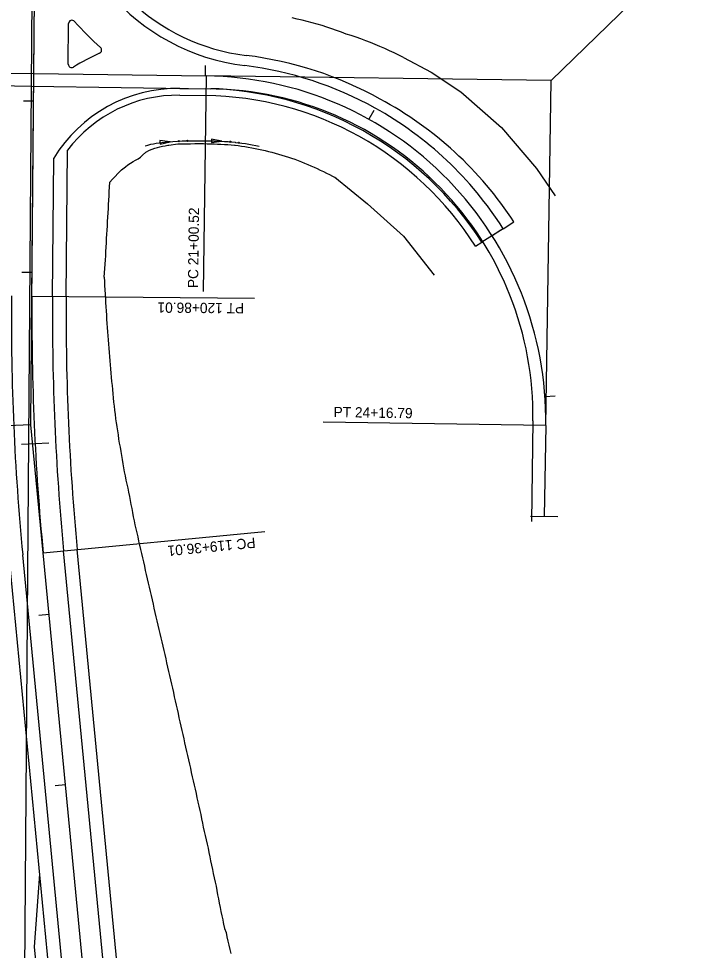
# Model space of a CAD drawing. Extents: x 1311167 to 1314552, y 2087587 to 2090602.
# Drawn here: x 1313998 to 1314395, y 2089699 to 2090242 of the extents above; entities that cross this region are included whole.
import ezdxf

# ---------------------------------------------------------------- set-up
doc = ezdxf.new("R2010")
doc.units = 0
for name, color, linetype in [('R_Bridge', 7, 'Continuous'), ('R_Guardrail', 7, 'Continuous'), ('R_Horz Alg Annot_Side Road', 7, 'Continuous'), ('R_Horz Alg Stationing', 7, 'Continuous'), ('R_Proposed Road', 7, 'Continuous'), ('R_Shld_GR', 7, 'Continuous'), ('R_Shoulder', 7, 'Continuous'), ('S_DITCHLINE', 7, 'Continuous'), ('S_EDGE_CONCRETE', 7, 'Continuous'), ('S_EDGE_PAVEMENT', 7, 'Continuous'), ('S_PAVEMENT_CROWN', 7, 'Continuous')]:
    doc.layers.add(name, color=color, linetype=linetype)

msp = doc.modelspace()

# ---------------------------------------------------------------- linework, layer by layer
at = {"layer": 'R_Bridge'}
for points in [[(1314000.32, 2090194.52), (1314006.32, 2090194.46)], [(1313999.45, 2090094.52), (1314005.45, 2090094.47)], [(1313999.17, 2089994.09), (1314015.15, 2089994.91)], [(1314009.35, 2089894.27), (1314015.32, 2089894.85)], [(1314018.93, 2089794.73), (1314024.9, 2089795.31)]]:
    msp.add_lwpolyline(points, dxfattribs=at)
at = {"layer": 'R_Guardrail'}
for points in [[(1314011.87, 2089930.69), (1314004.67, 2090005.41), (1314005.33, 2090080.47)], [(1314005.33, 2090080.47), (1314135.32, 2090079.34)], [(1314004.67, 2090005.41), (1313884.79, 2090000.17)], [(1314011.87, 2089930.69), (1314141.27, 2089943.15)]]:
    msp.add_lwpolyline(points, dxfattribs=at)
at = {"layer": 'R_Horz Alg Annot_Side Road'}
msp.add_line((1314007.85, 2089690.6), (1314006.9, 2089700.55), dxfattribs=at)
msp.add_lwpolyline([(1314006.9, 2089700.55), (1314009.84, 2089743.07)], dxfattribs=at)
at = {"layer": 'R_Horz Alg Stationing'}
for p, q in [((1313999.49, 2089462.84), (1314005.79, 2090288.55)), ((1313906.36, 2090204.65), (1314005.14, 2090203.15)), ((1314005.14, 2090203.15), (1314109.86, 2090201.56)), ((1314297.9, 2090007.65), (1314296.99, 2089948.94))]:
    msp.add_line(p, q, dxfattribs=at)
msp.add_arc((1314106.95, 2090010.61), 190.97, 359.1125, 89.1292, dxfattribs=at)
at = {"layer": 'R_Proposed Road'}
for p, q in [((1314005.29, 2090076.56), (1314006.99, 2090271.25)), ((1314005.33, 2090080.47), (1314006.99, 2090271.25)), ((1314005.33, 2090080.47), (1314006.99, 2090271.25)), ((1313908.73, 2090211.67), (1314006.46, 2090210.39)), ((1313908.73, 2090211.67), (1314006.46, 2090210.39)), ((1314006.46, 2090210.39), (1314106.97, 2090209.08)), ((1314006.46, 2090210.39), (1314106.97, 2090209.08)), ((1314305.36, 2090004.94), (1314304.53, 2089951.74)), ((1314305.36, 2090004.94), (1314304.53, 2089951.74)), ((1314055.57, 2089476.83), (1314011.87, 2089930.69)), ((1314055.57, 2089476.83), (1314011.87, 2089930.69))]:
    msp.add_line(p, q, dxfattribs=at)
for centre, radius, start, end in [((1314104.34, 2090008.05), 201.04, 359.1125, 89.25), ((1314104.34, 2090008.05), 201.04, 359.1125, 89.25), ((1315437.67, 2090067.97), 1432.39, 179.5, 185.5), ((1315437.67, 2090067.97), 1432.39, 179.5, 185.5)]:
    msp.add_arc(centre, radius, start, end, dxfattribs=at)
at = {"layer": 'R_Shld_GR'}
for points in [[(1314308.48, 2090206.44), (1314394.53, 2090290.07)], [(1314106.97, 2090209.08), (1314105.32, 2090083.14)], [(1314305.36, 2090004.94), (1314308.48, 2090206.44), (1314106.97, 2090209.08)], [(1314305.36, 2090004.94), (1314175.37, 2090006.95)]]:
    msp.add_lwpolyline(points, dxfattribs=at)
at = {"layer": 'R_Shoulder'}
for points in [[(1314106.53, 2090215.08), (1314106.45, 2090209.08)], [(1314205.04, 2090188.96), (1314202.12, 2090183.71)], [(1314279.15, 2090118.99), (1314274.09, 2090115.77)], [(1314310.9, 2090022.13), (1314304.91, 2090021.72)], [(1314312.53, 2089951.62), (1314296.53, 2089951.86)], [(1314312.53, 2089951.62), (1314296.53, 2089951.86)]]:
    msp.add_lwpolyline(points, dxfattribs=at)
at = {"layer": 'S_DITCHLINE'}
for p, q in [((1314086.13, 2090170.61), (1314080.08, 2090171.29)), ((1314080.08, 2090171.29), (1314080.21, 2090169.18)), ((1314080.21, 2090169.18), (1314086.13, 2090170.61)), ((1314110.19, 2090172.22), (1314110.12, 2090170.11)), ((1314110.12, 2090170.11), (1314116.15, 2090170.96)), ((1314116.15, 2090170.96), (1314110.19, 2090172.22))]:
    msp.add_line(p, q, dxfattribs=at)
for points in [[(1314071.37, 2090168.22), (1314073.02, 2090168.7), (1314074.67, 2090169.13), (1314076.32, 2090169.49), (1314077.95, 2090169.8), (1314079.58, 2090170.05), (1314081.21, 2090170.25), (1314082.82, 2090170.4), (1314084.43, 2090170.5), (1314084.96, 2090170.52), (1314092.99, 2090171.07), (1314095.49, 2090171.09), (1314097.99, 2090171.11), (1314100.49, 2090171.13), (1314102.99, 2090171.14), (1314105.49, 2090171.15), (1314107.7, 2090171.16), (1314109.73, 2090171.15), (1314111.76, 2090171.11), (1314113.79, 2090171.04), (1314115.82, 2090170.95), (1314117.85, 2090170.82), (1314119.87, 2090170.67), (1314121.9, 2090170.5), (1314123.92, 2090170.29), (1314124.22, 2090170.26), (1314125.94, 2090170.06), (1314127.95, 2090169.8), (1314129.97, 2090169.51), (1314131.98, 2090169.2), (1314133.98, 2090168.86), (1314135.98, 2090168.49), (1314137.98, 2090168.09)], [(1314071.37, 2090168.22), (1314073.02, 2090168.7), (1314074.67, 2090169.13), (1314076.32, 2090169.49), (1314077.95, 2090169.8), (1314079.58, 2090170.05), (1314081.21, 2090170.25), (1314082.82, 2090170.4), (1314084.43, 2090170.5), (1314084.96, 2090170.52), (1314086.13, 2090170.6)], [(1314101.12, 2090171.13), (1314101.15, 2090171.13)], [(1314101.15, 2090171.13), (1314102.99, 2090171.14), (1314105.49, 2090171.15), (1314107.7, 2090171.16), (1314109.73, 2090171.15), (1314111.76, 2090171.11), (1314113.79, 2090171.04), (1314115.82, 2090170.95), (1314116.15, 2090170.93)], [(1314131.06, 2090169.34), (1314131.1, 2090169.34)], [(1314131.1, 2090169.34), (1314131.98, 2090169.2), (1314133.98, 2090168.86), (1314135.98, 2090168.49), (1314137.98, 2090168.09)]]:
    msp.add_lwpolyline(points, dxfattribs=at)
for centre in [(1314091.12, 2090170.98), (1314096.13, 2090171.13), (1314121.14, 2090170.6), (1314126.13, 2090170.07)]:
    msp.add_circle(centre, 0.375, dxfattribs=at)
at = {"layer": 'S_EDGE_CONCRETE'}
for points in [[(1314222.24, 2090219.87), (1314219.53, 2090221.2), (1314216.81, 2090222.5), (1314214.08, 2090223.76), (1314211.33, 2090224.99), (1314208.57, 2090226.19), (1314205.8, 2090227.36), (1314203.01, 2090228.49), (1314200.22, 2090229.61), (1314197.41, 2090230.67), (1314194.59, 2090231.69), (1314191.71, 2090232.57), (1314188.84, 2090233.45), (1314186.1, 2090234.65), (1314183.27, 2090235.64), (1314180.43, 2090236.58), (1314177.57, 2090237.49), (1314174.72, 2090238.4), (1314171.84, 2090239.24), (1314168.95, 2090240.03), (1314166.06, 2090240.79), (1314163.16, 2090241.54), (1314160.25, 2090242.26), (1314157.33, 2090242.9)], [(1314222.24, 2090219.87), (1314238.55, 2090211.26), (1314255.87, 2090199.73), (1314279.52, 2090178.98), (1314299.98, 2090154.96), (1314310.86, 2090139.11)], [(1314071.74, 2090164.5), (1314074.06, 2090165.64), (1314075.54, 2090166.29), (1314077.03, 2090166.86), (1314078.55, 2090167.31), (1314080.07, 2090167.7), (1314081.6, 2090168.04), (1314083.13, 2090168.31), (1314084.66, 2090168.53), (1314085.17, 2090168.59), (1314090.46, 2090169.39), (1314092.96, 2090169.42), (1314095.47, 2090169.45), (1314097.97, 2090169.47), (1314100.47, 2090169.5), (1314102.97, 2090169.52), (1314105.47, 2090169.5), (1314107.67, 2090169.48), (1314109.68, 2090169.43), (1314111.68, 2090169.36), (1314113.69, 2090169.28), (1314115.7, 2090169.18), (1314117.7, 2090169.07), (1314119.71, 2090168.92), (1314121.71, 2090168.76), (1314123.71, 2090168.57), (1314124.01, 2090168.54), (1314125.71, 2090168.35), (1314127.71, 2090168.11), (1314129.7, 2090167.81), (1314131.68, 2090167.48), (1314133.66, 2090167.12), (1314135.64, 2090166.74), (1314137.61, 2090166.34)], [(1314050.75, 2090147.05), (1314052.35, 2090148.85), (1314054.01, 2090150.4), (1314055.43, 2090152.02), (1314056.85, 2090153.5), (1314057.55, 2090154.19), (1314058.34, 2090154.81), (1314059.87, 2090155.97), (1314061.38, 2090157.05), (1314062.87, 2090158.06), (1314064.36, 2090159), (1314065.83, 2090159.88), (1314067.3, 2090160.71), (1314068.71, 2090161.59), (1314069.94, 2090162.82), (1314071.74, 2090164.5)], [(1314137.61, 2090166.34), (1314139.57, 2090165.91), (1314141.53, 2090165.45), (1314143.48, 2090164.97), (1314145.43, 2090164.47), (1314147.37, 2090163.95), (1314149.31, 2090163.41), (1314151.24, 2090162.85), (1314153.17, 2090162.26), (1314155.08, 2090161.66), (1314156.99, 2090161.03), (1314158.9, 2090160.38), (1314160.8, 2090159.7), (1314162.67, 2090158.98), (1314164.53, 2090158.21), (1314166.38, 2090157.42), (1314168.22, 2090156.6), (1314170.06, 2090155.79), (1314171.89, 2090154.97), (1314173.72, 2090154.12), (1314175.53, 2090153.26), (1314177.34, 2090152.37), (1314179.14, 2090151.47), (1314180.92, 2090150.54), (1314182.7, 2090149.6), (1314183.03, 2090149.42)], [(1314047.49, 2090091.6), (1314047.64, 2090094.1), (1314047.97, 2090096.6), (1314048.11, 2090099.1), (1314048.25, 2090101.6), (1314048.38, 2090104.09), (1314048.52, 2090106.59), (1314048.66, 2090109.09), (1314048.8, 2090111.59), (1314048.94, 2090114.09), (1314049.08, 2090116.59), (1314049.23, 2090119.09), (1314049.38, 2090121.59), (1314049.53, 2090124.09), (1314049.67, 2090126.58), (1314049.81, 2090129.08), (1314049.94, 2090131.58), (1314050.06, 2090134.08), (1314050.19, 2090136.58), (1314050.33, 2090139.08), (1314050.46, 2090141.58), (1314050.6, 2090144.08), (1314050.75, 2090147.05)], [(1314182.14, 2090149.89), (1314201.36, 2090134.34), (1314222.29, 2090115.49), (1314240.23, 2090092.69)], [(1314047.49, 2090091.6), (1314047.62, 2090089.1), (1314047.75, 2090086.6), (1314047.89, 2090084.1), (1314048.04, 2090081.6), (1314048.19, 2090079.13), (1314048.33, 2090076.7), (1314048.48, 2090074.27), (1314048.62, 2090071.85), (1314048.78, 2090069.42), (1314048.94, 2090067), (1314049.11, 2090064.58), (1314049.29, 2090062.15), (1314049.48, 2090059.73), (1314049.66, 2090057.31), (1314049.84, 2090054.89), (1314050.02, 2090052.47), (1314050.21, 2090050.05), (1314050.4, 2090047.63), (1314050.59, 2090045.21), (1314050.79, 2090042.79), (1314050.99, 2090040.38), (1314051.19, 2090037.96), (1314051.41, 2090035.54), (1314051.63, 2090033.13), (1314051.84, 2090030.71), (1314052.07, 2090028.3), (1314052.29, 2090025.88), (1314052.52, 2090023.47), (1314052.76, 2090021.06), (1314053, 2090018.65), (1314053.28, 2090016.24), (1314053.58, 2090013.83), (1314053.89, 2090011.42), (1314054.2, 2090009.02), (1314054.38, 2090007.58), (1314054.52, 2090006.61), (1314054.87, 2090004.21), (1314055.22, 2090001.81), (1314055.58, 2089999.41), (1314055.94, 2089997.01), (1314056.33, 2089994.61), (1314056.78, 2089992.22), (1314057.22, 2089989.82), (1314057.61, 2089987.43), (1314058.02, 2089985.04), (1314058.43, 2089982.64), (1314058.84, 2089980.25), (1314059.26, 2089977.87), (1314059.73, 2089975.48), (1314060.24, 2089973.1), (1314060.76, 2089970.72), (1314061.28, 2089968.34), (1314061.75, 2089965.96), (1314062.2, 2089963.58), (1314062.65, 2089961.2), (1314063.11, 2089958.82), (1314063.58, 2089956.45), (1314064.05, 2089954.07), (1314064.52, 2089951.7), (1314065, 2089949.33), (1314065.49, 2089946.95), (1314065.99, 2089944.58), (1314066.53, 2089942.22), (1314067.07, 2089939.86), (1314067.61, 2089937.5), (1314068.16, 2089935.1), (1314068.72, 2089932.64), (1314069.28, 2089930.18), (1314069.84, 2089927.72), (1314070.41, 2089925.27), (1314070.97, 2089922.81), (1314071.51, 2089920.35), (1314072.05, 2089917.89), (1314072.61, 2089915.43), (1314073.18, 2089912.98), (1314073.75, 2089910.52), (1314074.32, 2089908.06), (1314074.89, 2089905.61), (1314075.47, 2089903.15), (1314076.03, 2089900.69), (1314076.58, 2089898.23), (1314077.13, 2089895.78), (1314077.7, 2089893.32), (1314078.27, 2089890.86), (1314078.85, 2089888.41), (1314079.43, 2089885.95), (1314080.02, 2089883.49), (1314080.59, 2089881.04), (1314081.16, 2089878.58), (1314081.73, 2089876.12), (1314082.29, 2089873.67), (1314082.86, 2089871.21), (1314083.42, 2089868.75), (1314083.98, 2089866.3), (1314084.54, 2089863.84), (1314085.1, 2089861.38), (1314085.67, 2089858.92), (1314086.24, 2089856.47), (1314086.8, 2089854.01), (1314087.35, 2089851.55), (1314087.9, 2089849.09), (1314088.45, 2089846.63), (1314088.99, 2089844.17), (1314089.53, 2089841.71), (1314090.07, 2089839.26), (1314090.63, 2089836.8), (1314091.19, 2089834.34), (1314091.74, 2089831.88), (1314092.3, 2089829.42), (1314092.85, 2089826.96), (1314093.39, 2089824.5), (1314093.93, 2089822.05), (1314094.47, 2089819.59), (1314095.03, 2089817.13), (1314095.59, 2089814.67), (1314096.15, 2089812.21), (1314096.71, 2089809.76), (1314097.27, 2089807.3), (1314097.83, 2089804.84), (1314098.39, 2089802.38), (1314098.95, 2089799.92), (1314099.5, 2089797.47), (1314100.04, 2089795.01), (1314100.58, 2089792.55), (1314101.13, 2089790.09), (1314101.69, 2089787.63), (1314102.25, 2089785.17), (1314102.26, 2089785.11), (1314102.81, 2089782.72), (1314103.37, 2089780.26), (1314103.89, 2089777.8), (1314104.37, 2089775.33), (1314104.85, 2089772.87), (1314105.38, 2089770.41), (1314105.95, 2089767.95), (1314106.52, 2089765.49), (1314107.08, 2089763.03), (1314107.65, 2089760.58), (1314108.21, 2089758.12), (1314108.7, 2089755.66), (1314109.16, 2089753.19), (1314109.63, 2089750.72), (1314110.13, 2089748.26), (1314110.67, 2089745.8), (1314111.22, 2089743.34), (1314111.77, 2089740.88), (1314112.31, 2089738.42), (1314112.85, 2089735.96), (1314113.3, 2089733.49), (1314113.75, 2089731.03), (1314114.19, 2089728.56), (1314114.67, 2089726.09), (1314115.2, 2089723.63), (1314115.72, 2089721.17), (1314116.25, 2089718.71), (1314116.77, 2089716.25), (1314117.08, 2089714.78), (1314117.27, 2089713.78), (1314117.7, 2089711.31), (1314118.65, 2089708.94), (1314118.66, 2089708.89), (1314119.17, 2089706.43), (1314119.7, 2089703.97), (1314120.29, 2089701.52), (1314120.87, 2089699.06), (1314121.46, 2089696.61)]]:
    msp.add_lwpolyline(points, dxfattribs=at)
at = {"layer": 'S_EDGE_PAVEMENT'}
for p, q in [((1314091.71, 2090197.77), (1314106.82, 2090197.58)), ((1314025.33, 2090080.3), (1314026.07, 2090165.68)), ((1314280.55, 2090119.87), (1314286.77, 2090123.82)), ((1314264.38, 2090109.61), (1314268, 2090111.91)), ((1314075.48, 2089478.75), (1314031.77, 2089932.6)), ((1314035.66, 2089474.91), (1313991.96, 2089928.77))]:
    msp.add_line(p, q, dxfattribs=at)
for centre, radius, start, end in [((1314144.91, 2090339.12), 119, 189.5746, 263.0143), ((1314104.34, 2090008.05), 214.54, 60.8986, 82.9962), ((1314090.65, 2090116.78), 81, 89.25, 142.8665), ((1314104.34, 2090008.05), 189.54, 60.8986, 89.25), ((1314107.14, 2090006.52), 214.54, 33.145, 61.7515), ((1314104.34, 2090008.05), 189.54, 32.3985, 60.8986), ((1315437.67, 2090067.97), 1412.39, 179.5, 185.5)]:
    msp.add_arc(centre, radius, start, end, dxfattribs=at)
at = {"layer": 'S_PAVEMENT_CROWN'}
for p, q in [((1314026.51, 2090215.93), (1314026.72, 2090239.59)), ((1314091.76, 2090201.77), (1314106.88, 2090201.58)), ((1314017.33, 2090080.37), (1314018.03, 2090160.96)), ((1314280.55, 2090119.87), (1314267.99, 2090111.91)), ((1314043.62, 2089475.68), (1313999.92, 2089929.54)), ((1314067.51, 2089477.98), (1314023.81, 2089931.84))]:
    msp.add_line(p, q, dxfattribs=at)
for centre, radius, start, end in [((1314144.91, 2090339.12), 125, 178.9726, 263.0143), ((1314028.72, 2090239.57), 2, 40.5871, 179.5), ((1314144.91, 2090339.12), 151, 220.5871, 228.7474), ((1314044.02, 2090224.09), 2, 293.4847, 48.7474), ((1314090.65, 2090116.78), 115, 113.4847, 122.079), ((1314028.51, 2090215.92), 2, 179.5, 302.079), ((1314104.34, 2090008.05), 208.54, 60.8986, 83.0143), ((1314090.65, 2090116.78), 85, 89.25, 148.6847), ((1314104.34, 2090008.05), 193.54, 60.8986, 89.25), ((1314104.62, 2090007.9), 208.54, 32.4747, 60.9853), ((1314104.86, 2090007.77), 193.54, 32.5535, 61.0751), ((1315437.67, 2090067.97), 1444.39, 179.5, 185.5), ((1315437.67, 2090067.97), 1420.39, 179.5, 185.5)]:
    msp.add_arc(centre, radius, start, end, dxfattribs=at)

# ---------------------------------------------------------------- texts
at = {"layer": 'R_Guardrail'}
for s, rotation, p in [('PT 120+86.01', 179.5, (1314129.3, 2090076.39)), ('PC 119+36.01', 185.5, (1314135.58, 2089939.58))]:
    msp.add_text(s, height=6, rotation=rotation, dxfattribs=at).set_placement(p)
at = {"layer": 'R_Shld_GR'}
for s, rotation, p in [('PC 21+00.52', 89.25, (1314102.35, 2090085.12)), ('PT 24+16.79', 359.1125, (1314181.42, 2090009.86))]:
    msp.add_text(s, height=6, rotation=rotation, dxfattribs=at).set_placement(p)

doc.saveas('drawing.dxf')
